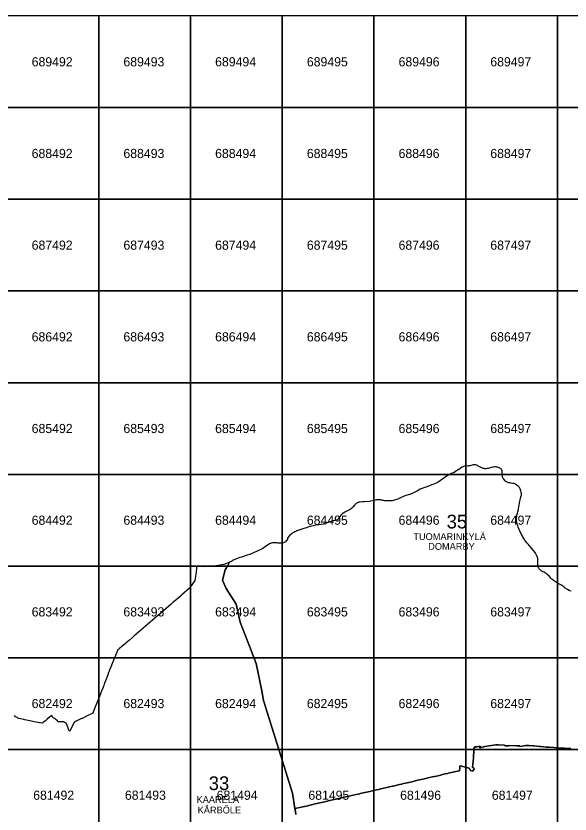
# Model space of a CAD drawing. Extents: x 25485000 to 25520000, y 6656775 to 6690000.
# Drawn here: x 25492097 to 25498138, y 6681295 to 6690000 of the extents above; entities that cross this region are included whole.
import ezdxf

# ---------------------------------------------------------------- set-up
doc = ezdxf.new("R2010")
doc.units = 0
doc.layers.add('Level 63', color=7, linetype='Continuous')

msp = doc.modelspace()

# ---------------------------------------------------------------- linework, layer by layer
at = {"layer": 'Level 63'}
for points in [[(25492000, 6689000), (25493000, 6689000), (25493000, 6690000), (25492000, 6690000)], [(25493000, 6689000), (25494000, 6689000), (25494000, 6690000), (25493000, 6690000)], [(25494000, 6689000), (25495000, 6689000), (25495000, 6690000), (25494000, 6690000)], [(25495000, 6689000), (25496000, 6689000), (25496000, 6690000), (25495000, 6690000)], [(25496000, 6689000), (25497000, 6689000), (25497000, 6690000), (25496000, 6690000)], [(25497000, 6689000), (25498000, 6689000), (25498000, 6690000), (25497000, 6690000)], [(25498000, 6689000), (25499000, 6689000), (25499000, 6690000), (25498000, 6690000)], [(25492000, 6688000), (25493000, 6688000), (25493000, 6689000), (25492000, 6689000)], [(25493000, 6688000), (25494000, 6688000), (25494000, 6689000), (25493000, 6689000)], [(25494000, 6688000), (25495000, 6688000), (25495000, 6689000), (25494000, 6689000)], [(25495000, 6688000), (25496000, 6688000), (25496000, 6689000), (25495000, 6689000)], [(25496000, 6688000), (25497000, 6688000), (25497000, 6689000), (25496000, 6689000)], [(25497000, 6688000), (25498000, 6688000), (25498000, 6689000), (25497000, 6689000)], [(25498000, 6688000), (25499000, 6688000), (25499000, 6689000), (25498000, 6689000)], [(25492000, 6687000), (25493000, 6687000), (25493000, 6688000), (25492000, 6688000)], [(25493000, 6687000), (25494000, 6687000), (25494000, 6688000), (25493000, 6688000)], [(25494000, 6687000), (25495000, 6687000), (25495000, 6688000), (25494000, 6688000)], [(25495000, 6687000), (25496000, 6687000), (25496000, 6688000), (25495000, 6688000)], [(25496000, 6687000), (25497000, 6687000), (25497000, 6688000), (25496000, 6688000)], [(25497000, 6687000), (25498000, 6687000), (25498000, 6688000), (25497000, 6688000)], [(25498000, 6687000), (25499000, 6687000), (25499000, 6688000), (25498000, 6688000)], [(25492000, 6686000), (25493000, 6686000), (25493000, 6687000), (25492000, 6687000)], [(25493000, 6686000), (25494000, 6686000), (25494000, 6687000), (25493000, 6687000)], [(25494000, 6686000), (25495000, 6686000), (25495000, 6687000), (25494000, 6687000)], [(25495000, 6686000), (25496000, 6686000), (25496000, 6687000), (25495000, 6687000)], [(25496000, 6686000), (25497000, 6686000), (25497000, 6687000), (25496000, 6687000)], [(25497000, 6686000), (25498000, 6686000), (25498000, 6687000), (25497000, 6687000)], [(25498000, 6686000), (25499000, 6686000), (25499000, 6687000), (25498000, 6687000)], [(25492000, 6685000), (25493000, 6685000), (25493000, 6686000), (25492000, 6686000)], [(25493000, 6685000), (25494000, 6685000), (25494000, 6686000), (25493000, 6686000)], [(25494000, 6685000), (25495000, 6685000), (25495000, 6686000), (25494000, 6686000)], [(25495000, 6685000), (25496000, 6685000), (25496000, 6686000), (25495000, 6686000)], [(25496000, 6685000), (25497000, 6685000), (25497000, 6686000), (25496000, 6686000)], [(25497000, 6685000), (25498000, 6685000), (25498000, 6686000), (25497000, 6686000)], [(25498000, 6685000), (25499000, 6685000), (25499000, 6686000), (25498000, 6686000)], [(25492000, 6684000), (25493000, 6684000), (25493000, 6685000), (25492000, 6685000)], [(25493000, 6684000), (25494000, 6684000), (25494000, 6685000), (25493000, 6685000)], [(25494000, 6684000), (25495000, 6684000), (25495000, 6685000), (25494000, 6685000)], [(25495000, 6684000), (25496000, 6684000), (25496000, 6685000), (25495000, 6685000)], [(25496000, 6684000), (25497000, 6684000), (25497000, 6685000), (25496000, 6685000)], [(25497000, 6684000), (25498000, 6684000), (25498000, 6685000), (25497000, 6685000)], [(25498000, 6684000), (25499000, 6684000), (25499000, 6685000), (25498000, 6685000)], [(25492000, 6683000), (25493000, 6683000), (25493000, 6684000), (25492000, 6684000)], [(25493000, 6683000), (25494000, 6683000), (25494000, 6684000), (25493000, 6684000)], [(25494000, 6683000), (25495000, 6683000), (25495000, 6684000), (25494000, 6684000)], [(25495000, 6683000), (25496000, 6683000), (25496000, 6684000), (25495000, 6684000)], [(25496000, 6683000), (25497000, 6683000), (25497000, 6684000), (25496000, 6684000)], [(25497000, 6683000), (25498000, 6683000), (25498000, 6684000), (25497000, 6684000)], [(25498000, 6683000), (25499000, 6683000), (25499000, 6684000), (25498000, 6684000)], [(25492000, 6682000), (25493000, 6682000), (25493000, 6683000), (25492000, 6683000)], [(25493000, 6682000), (25494000, 6682000), (25494000, 6683000), (25493000, 6683000)], [(25494000, 6682000), (25495000, 6682000), (25495000, 6683000), (25494000, 6683000)], [(25495000, 6682000), (25496000, 6682000), (25496000, 6683000), (25495000, 6683000)], [(25496000, 6682000), (25497000, 6682000), (25497000, 6683000), (25496000, 6683000)], [(25497000, 6682000), (25498000, 6682000), (25498000, 6683000), (25497000, 6683000)], [(25498000, 6682000), (25499000, 6682000), (25499000, 6683000), (25498000, 6683000)], [(25492000, 6681000), (25493000, 6681000), (25493000, 6682000), (25492000, 6682000)], [(25493000, 6681000), (25494000, 6681000), (25494000, 6682000), (25493000, 6682000)], [(25494000, 6681000), (25495000, 6681000), (25495000, 6682000), (25494000, 6682000)], [(25495000, 6681000), (25496000, 6681000), (25496000, 6682000), (25495000, 6682000)], [(25496000, 6681000), (25497000, 6681000), (25497000, 6682000), (25496000, 6682000)], [(25497000, 6681000), (25498000, 6681000), (25498000, 6682000), (25497000, 6682000)], [(25498000, 6681000), (25499000, 6681000), (25499000, 6682000), (25498000, 6682000)]]:
    msp.add_lwpolyline(points, close=True, dxfattribs=at)
for points in [[(25498148.4, 6683726.5), (25498136.8, 6683730.8), (25498128.7, 6683734.6), (25498111.2, 6683744), (25498086.2, 6683760), (25498071.1, 6683771.5), (25498036.2, 6683793.2), (25497989.5, 6683820.3), (25497978.1, 6683827.7), (25497967.6, 6683835.1), (25497957.9, 6683842.3), (25497948.6, 6683849.8), (25497939.1, 6683857.9), (25497930.1, 6683866.4), (25497912.1, 6683884.4), (25497885, 6683909.9), (25497872.6, 6683920.8), (25497865.7, 6683925.6), (25497854.3, 6683931.3), (25497842.7, 6683936.5), (25497829, 6683943.6), (25497822.6, 6683948), (25497812.1, 6683957.8), (25497802.5, 6683968.9), (25497798.4, 6683975.4), (25497795.4, 6683982), (25497793.2, 6683987.9), (25497789.3, 6684001), (25497786.4, 6684013.5), (25497785.6, 6684020.3), (25497785.7, 6684029.7), (25497787.4, 6684050.4), (25497787.7, 6684064.8), (25497787, 6684076.6), (25497786, 6684082.9), (25497784, 6684092.7), (25497780.8, 6684102.2), (25497776.4, 6684112.2), (25497769.6, 6684124.8), (25497760.8, 6684138.6), (25497752.8, 6684150.4), (25497702.9, 6684214.5), (25497693.5, 6684224.7), (25497683.8, 6684234.5), (25497667.4, 6684252.9), (25497659.7, 6684262.1), (25497652.1, 6684272.1), (25497645.9, 6684280.9), (25497640.1, 6684289.8), (25497634, 6684299.8), (25497609.6, 6684344.3), (25497603.8, 6684355.8), (25497598.2, 6684366.5), (25497573.7, 6684423.7), (25497568.1, 6684438.4), (25497562.6, 6684454.8), (25497559.3, 6684466.4), (25497556.8, 6684477.6), (25497555.3, 6684487.8), (25497554.7, 6684494.6), (25497554.3, 6684505.3), (25497554.2, 6684515.8), (25497555.4, 6684533.4), (25497556.8, 6684543.5), (25497559, 6684553.5), (25497565.7, 6684576.9), (25497569, 6684589.5), (25497575.3, 6684615.2), (25497577.3, 6684627.5), (25497579.2, 6684645.2), (25497582.6, 6684665.6), (25497590.6, 6684708), (25497593.7, 6684722), (25497597.3, 6684736), (25497602.9, 6684753.5), (25497606, 6684765.4), (25497607.4, 6684773.8), (25497607.9, 6684783.6), (25497607.3, 6684795), (25497605.9, 6684805.4), (25497602.9, 6684818.4), (25497599.1, 6684830.1), (25497594.3, 6684841.4), (25497590.2, 6684848.9), (25497585.7, 6684855.5), (25497579.8, 6684862.3), (25497570.9, 6684871.2), (25497560.9, 6684879.7), (25497550.7, 6684887.2), (25497542.5, 6684892.1), (25497534.6, 6684896.1), (25497527.1, 6684899.1), (25497515.4, 6684901.6), (25497495, 6684904.2), (25497483.3, 6684906.2), (25497471.3, 6684908.7), (25497460.8, 6684911.3), (25497454.2, 6684913.7), (25497443.7, 6684918.9), (25497436.7, 6684923.6), (25497434.3, 6684925.8), (25497430, 6684929.7), (25497415.3, 6684946.5), (25497409.4, 6684955.3), (25497406.2, 6684962), (25497402.4, 6684973.1), (25497400.1, 6684984.6), (25497398.9, 6684996.7), (25497398.5, 6685021.1), (25497398, 6685030.3), (25497396.4, 6685039.3), (25497393.3, 6685048.6), (25497389.9, 6685054.6), (25497385.2, 6685060), (25497379.4, 6685064.5), (25497372.6, 6685068.1), (25497359.1, 6685073.5), (25497348.2, 6685077.1), (25497337.4, 6685079.3), (25497325.6, 6685080.2), (25497318.5, 6685080.3), (25497302.2, 6685078.3), (25497293.9, 6685076.8), (25497266.8, 6685070.2), (25497243.5, 6685065.2), (25497231.4, 6685063.3), (25497219, 6685061.7), (25497210, 6685061.4), (25497201.6, 6685062.1), (25497194.7, 6685063.1), (25497184.8, 6685065.7), (25497181.5, 6685066.9), (25497174.8, 6685069.4), (25497159.9, 6685077.1), (25497149.5, 6685083.1), (25497137.8, 6685090.2), (25497128.5, 6685095.8), (25497119.3, 6685100.2), (25497110.8, 6685103), (25497103.7, 6685104.2), (25497093.6, 6685103.9), (25497081.7, 6685102.1), (25497046.8, 6685093.6), (25497034.7, 6685091.4), (25497028.9, 6685090.8), (25497022.4, 6685090.9), (25497010.5, 6685092.5), (25496998.4, 6685092.9), (25496992.9, 6685092.3), (25496987, 6685091), (25496976.5, 6685086.7), (25496962.2, 6685078.4), (25496944.4, 6685067.2), (25496935.4, 6685060.8), (25496918.7, 6685049.1), (25496888.2, 6685029.6), (25496874.6, 6685021.8), (25496861.8, 6685015.7), (25496844.9, 6685008.2), (25496827.6, 6684999.8), (25496808.3, 6684989.4), (25496790.2, 6684979), (25496760.1, 6684957.8), (25496700.7, 6684914.7), (25496693.9, 6684911), (25496686.2, 6684907.2), (25496677.7, 6684903.5), (25496641, 6684889.8), (25496627.8, 6684885.1), (25496618.8, 6684881.8), (25496604.4, 6684875.8), (25496505.2, 6684838.5), (25496484.3, 6684826), (25496473.4, 6684820.1), (25496452.2, 6684808), (25496410.7, 6684786.6), (25496399.1, 6684782.2), (25496361.8, 6684774), (25496348.8, 6684770.6), (25496335.6, 6684766), (25496291.1, 6684745.3), (25496259.4, 6684730.1), (25496247.1, 6684725.1), (25496234.8, 6684720.6), (25496221.7, 6684717.1), (25496209.6, 6684714.6), (25496197, 6684712.5), (25496183.8, 6684711), (25496170.7, 6684710), (25496156.7, 6684709.8), (25496118.5, 6684712.2), (25496106.3, 6684713.6), (25496094.2, 6684716.3), (25496083.3, 6684718.9), (25496075.3, 6684720.3), (25496047.8, 6684722.3), (25496036.1, 6684722.1), (25496023.9, 6684720.4), (25496012.2, 6684718), (25495983, 6684710.9), (25495967.7, 6684707.8), (25495952, 6684705.4), (25495891.5, 6684700.5), (25495874.5, 6684699.1), (25495850.4, 6684698.2), (25495843.3, 6684697.4), (25495833.8, 6684695.7), (25495826.6, 6684693.5), (25495818.1, 6684689.4), (25495809.8, 6684683.5), (25495802, 6684677), (25495789, 6684663.3), (25495773.7, 6684645), (25495766.9, 6684638.4), (25495755.5, 6684628.9), (25495746, 6684621.6), (25495732.2, 6684611.8), (25495726.5, 6684608.5), (25495682.7, 6684586.6), (25495673.1, 6684581.1), (25495663.5, 6684575.3), (25495653.9, 6684568.6), (25495644.7, 6684561), (25495639.6, 6684555.6), (25495627.5, 6684541.8), (25495624, 6684536.6), (25495617.7, 6684526), (25495611.4, 6684513.5), (25495606.9, 6684507.6), (25495602.2, 6684503.8), (25495587.8, 6684501), (25495571.7, 6684497.5), (25495553.3, 6684492.4), (25495543, 6684489), (25495506.3, 6684477.8), (25495498.3, 6684474.8), (25495482.6, 6684468.2), (25495467.5, 6684462.7), (25495460.3, 6684460.5), (25495448.3, 6684457.9), (25495425.6, 6684454.2), (25495401.6, 6684450.5), (25495365.4, 6684444.4), (25495309.1, 6684432.5), (25495297.1, 6684429.3), (25495263.8, 6684418.2), (25495236.3, 6684407.7), (25495213.9, 6684400.3), (25495181.5, 6684390.9), (25495169.4, 6684386.8), (25495158.9, 6684382.8), (25495148, 6684378), (25495136.5, 6684372.5), (25495126.8, 6684366.8), (25495117.1, 6684361), (25495107.3, 6684354.2), (25495098.2, 6684347.4), (25495089, 6684339.7), (25495080.4, 6684331.8), (25495068.6, 6684320.1), (25495064.2, 6684314), (25495059.2, 6684303.4), (25495055.6, 6684292.5), (25495050.8, 6684282.7), (25495043.8, 6684273.2), (25495035.5, 6684264.9), (25495028.7, 6684259.7), (25495020.6, 6684254.9), (25495012.1, 6684251.3), (25495002.1, 6684248.7), (25494990.1, 6684247.6), (25494977.1, 6684247.8), (25494952.9, 6684249.8), (25494940.8, 6684251.4), (25494928.8, 6684252.8), (25494915.8, 6684253.6), (25494903.6, 6684253.4), (25494892.2, 6684252.1), (25494880.3, 6684249.4), (25494872.8, 6684246.7), (25494867, 6684243.9), (25494850.5, 6684233.6), (25494802.5, 6684200.7), (25494787.5, 6684191.5), (25494775.5, 6684184.8), (25494765, 6684179.4), (25494688.4, 6684145.2), (25494652.4, 6684131), (25494607.4, 6684114.3), (25494556.9, 6684096.8), (25494538.4, 6684091.9), (25494481.8, 6684072.7), (25494474.3, 6684069.1), (25494466.1, 6684064.2), (25494454.1, 6684055.8), (25494445.1, 6684050.5), (25494434.8, 6684045), (25494425.3, 6684040.6), (25494401.8, 6684000), (25494379, 6683957.1), (25494349.6, 6683845.6), (25494389.9, 6683753.1), (25494498, 6683585.2), (25494539.7, 6683387.4), (25494642.3, 6683127.1), (25494717.5, 6682937.4), (25494775.8, 6682637.7), (25494796.1, 6682533.7), (25495110.2, 6681520.8), (25495138.2, 6681354.6), (25495172.3, 6681362.1), (25495206.5, 6681370.8), (25495241.2, 6681377.6), (25495259.8, 6681381.5), (25495281.4, 6681385.9), (25495286.7, 6681387), (25495303.3, 6681392), (25495320.2, 6681396.1), (25495357.5, 6681404.4), (25495375.5, 6681408.6), (25495393.5, 6681412.7), (25495429.6, 6681420.9), (25495466.1, 6681429.2), (25495502.4, 6681437.4), (25495534.3, 6681445), (25495566.2, 6681452.6), (25495645.6, 6681471.4), (25495669.4, 6681476.9), (25495693.1, 6681482.3), (25495716.9, 6681487.6), (25495740.8, 6681493), (25495805.9, 6681507.7), (25495830.3, 6681513.1), (25495862.9, 6681520.5), (25495954.5, 6681541.4), (25495979.9, 6681547.2), (25496003.4, 6681552.6), (25496026.1, 6681557.9), (25496051.9, 6681564), (25496071.5, 6681568.4), (25496075.9, 6681569.4), (25496106.2, 6681576.2), (25496140.1, 6681583.9), (25496170.6, 6681590.9), (25496202.3, 6681598.2), (25496209.6, 6681600), (25496276.9, 6681616), (25496299.5, 6681621.2), (25496322, 6681626.5), (25496344.6, 6681631.7), (25496379.4, 6681639.8), (25496413.5, 6681647.7), (25496478.8, 6681662.5), (25496513.1, 6681670.4), (25496546.7, 6681678.3), (25496605.4, 6681692.1), (25496639.4, 6681699.9), (25496680.9, 6681708.7), (25496713.3, 6681716.4), (25496746.2, 6681724.3), (25496777, 6681731.4), (25496802, 6681737.2), (25496810.3, 6681739.1), (25496826.3, 6681742.8), (25496874.9, 6681754.2), (25496931.7, 6681767.2), (25496932.1, 6681767), (25496935.5, 6681801.9), (25496936.8, 6681815.1), (25496943.2, 6681819.7), (25497036.7, 6681796.3), (25497052.7, 6681769.7), (25497075.9, 6681763.9), (25497091.8, 6681784.7), (25497090.1, 6681799.6), (25497074.9, 6681803.4), (25497077.8, 6681838.8), (25497079.9, 6681863.7), (25497084, 6681913.5), (25497086.8, 6681946.9), (25497087.2, 6681952.6), (25497089.6, 6681982.6), (25497091.6, 6682007.3), (25497093, 6682024.3), (25497102.7, 6682025.9), (25497122.9, 6682029.3), (25497156.9, 6682034.9), (25497155.3, 6682015.5), (25497195.2, 6682027.4), (25497207.1, 6682030.9), (25497210.1, 6682031.4), (25497255.4, 6682038.3), (25497280.5, 6682042.3), (25497302.8, 6682045.6), (25497330, 6682049.6), (25497343.3, 6682049.2), (25497358.8, 6682048.4), (25497423.7, 6682046.1), (25497426.4, 6682042), (25497426.3, 6682040), (25497469.8, 6682037.9), (25497470.2, 6682043.8), (25497554.8, 6682039.5), (25497586, 6682038), (25497590.4, 6682030.7), (25497637.5, 6682040), (25497655.8, 6682043.5), (25497678.4, 6682041.5), (25497689.3, 6682040.8), (25497730.6, 6682038.1), (25497736.6, 6682037.5), (25497742.3, 6682037), (25497772.2, 6682034.4), (25497807.1, 6682031.1), (25497819.1, 6682030.4), (25497878.8, 6682025.3), (25497881.4, 6682025.1), (25497909.6, 6682023.1), (25498009.3, 6682017.8), (25498145.5, 6682010.5)], [(25495149.3, 6681289.5), (25495143.9, 6681321.9), (25495138.2, 6681354.6), (25495110.2, 6681520.8), (25494796.1, 6682533.7), (25494775.8, 6682637.7), (25494717.5, 6682937.4), (25494642.3, 6683127.1), (25494539.7, 6683387.4), (25494498, 6683585.2), (25494389.9, 6683753.1), (25494349.6, 6683845.6), (25494379, 6683957.1), (25494401.8, 6684000), (25494425.3, 6684040.6), (25494385, 6684025), (25494362.8, 6684017.7), (25494342.8, 6684011.8), (25494328.3, 6684008.9), (25494299.8, 6684004.6), (25494250.4, 6683998.2), (25494207.7, 6683993.8), (25494186.7, 6683993), (25494150.9, 6683992.4), (25494089.7, 6683995.1), (25494068.1, 6683996), (25494066.7, 6683984.5), (25494066.4, 6683981.9), (25494065.2, 6683972.7), (25494060.6, 6683935.5), (25494051.4, 6683865.5), (25494048.7, 6683842.4), (25493989.3, 6683757.9), (25493906.2, 6683685.6), (25493903.1, 6683682.9), (25493892.7, 6683673.9), (25493864.6, 6683649.3), (25493839.7, 6683628.9), (25493811.9, 6683604.6), (25493788.9, 6683584.5), (25493680.7, 6683489.9), (25493677.5, 6683487.1), (25493671.4, 6683481.9), (25493641.1, 6683457), (25493635, 6683451.7), (25493632.5, 6683449.6), (25493614.3, 6683433.9), (25493610.5, 6683430.7), (25493383.6, 6683234.9), (25493366.9, 6683220.6), (25493333.1, 6683191.5), (25493298.3, 6683161.8), (25493295.9, 6683159.6), (25493292, 6683156.4), (25493250.8, 6683121.2), (25493226, 6683099.8), (25493225.5, 6683099.6), (25493219.5, 6683094.4), (25493213.5, 6683088.7), (25493211.9, 6683087.7), (25493204.6, 6683081.4), (25493203, 6683077.4), (25493191.9, 6683049.6), (25493185.8, 6683034.4), (25493181.4, 6683023.3), (25493175, 6683007.3), (25493139.5, 6682918.8), (25493137.8, 6682914.3), (25493125.6, 6682883.5), (25493114.4, 6682855.1), (25493112.3, 6682849.7), (25493109.6, 6682842.9), (25493107.7, 6682838.1), (25493099.1, 6682814.8), (25493083.1, 6682773.8), (25493072.5, 6682746), (25493063.3, 6682722.3), (25493058.2, 6682709.3), (25493046.2, 6682678.3), (25493032, 6682641.6), (25493031.3, 6682639.7), (25493026.9, 6682628.2), (25493003.1, 6682567.1), (25492999.3, 6682557.5), (25492982.4, 6682514.3), (25492961.9, 6682462.3), (25492935.5, 6682394.9), (25492872.1, 6682364.4), (25492840.4, 6682349.2), (25492818, 6682338.3), (25492805.3, 6682332.1), (25492753.4, 6682307.3), (25492750.5, 6682305.9), (25492741, 6682301.4), (25492733.1, 6682297.6), (25492683.7, 6682198.9), (25492673.9, 6682207.4), (25492670.1, 6682212.9), (25492668.9, 6682216.9), (25492669, 6682225.3), (25492668.2, 6682230), (25492667.9, 6682231.3), (25492661.6, 6682248.2), (25492660.3, 6682250.8), (25492651.1, 6682269.7), (25492643, 6682284.4), (25492638.8, 6682288.4), (25492625.9, 6682294.5), (25492614.6, 6682299.5), (25492607, 6682300.1), (25492584.9, 6682299.9), (25492575.7, 6682299.1), (25492566.4, 6682300.3), (25492559, 6682302.1), (25492554.1, 6682304.4), (25492548.3, 6682309.6), (25492536.1, 6682323.6), (25492529.1, 6682329.1), (25492517.4, 6682335.9), (25492504.3, 6682345.8), (25492497.9, 6682352.1), (25492493.5, 6682360.3), (25492486.6, 6682370.5), (25492463.5, 6682350.7), (25492432.9, 6682324.7), (25492414.9, 6682309.4), (25492412.9, 6682307.7), (25492394.2, 6682291.8), (25492385.8, 6682284.6), (25492361.5, 6682289.5), (25492355, 6682290.9), (25492195.2, 6682323.1), (25492183, 6682325.6), (25492126.9, 6682336.9), (25492117.7, 6682342.2), (25492108.5, 6682347.6), (25492100.5, 6682352.2), (25492077.7, 6682365.4)], [(25498145.5, 6682010.5), (25498009.3, 6682017.8), (25497909.6, 6682023.1), (25497881.4, 6682025.1), (25497878.8, 6682025.3), (25497819.1, 6682030.4), (25497807.1, 6682031.1), (25497772.2, 6682034.4), (25497742.3, 6682037), (25497736.6, 6682037.5), (25497730.6, 6682038.1), (25497689.3, 6682040.8), (25497678.4, 6682041.5), (25497655.8, 6682043.5), (25497637.5, 6682040), (25497590.4, 6682030.7), (25497586, 6682038), (25497554.8, 6682039.5), (25497470.2, 6682043.8), (25497469.8, 6682037.9), (25497426.3, 6682040), (25497426.4, 6682042), (25497423.7, 6682046.1), (25497358.8, 6682048.4), (25497343.3, 6682049.2), (25497330, 6682049.6), (25497302.8, 6682045.6), (25497280.5, 6682042.3), (25497255.4, 6682038.3), (25497210.1, 6682031.4), (25497207.1, 6682030.9), (25497195.2, 6682027.4), (25497155.3, 6682015.5), (25497156.9, 6682034.9), (25497122.9, 6682029.3), (25497102.7, 6682025.9), (25497093, 6682024.3), (25497091.6, 6682007.3), (25497089.6, 6681982.6), (25497087.2, 6681952.6), (25497086.8, 6681946.9), (25497084, 6681913.5), (25497079.9, 6681863.7), (25497077.8, 6681838.8), (25497074.9, 6681803.4), (25497090.1, 6681799.6), (25497091.8, 6681784.7), (25497075.9, 6681763.9), (25497052.7, 6681769.7), (25497036.7, 6681796.3), (25496943.2, 6681819.7), (25496936.8, 6681815.1), (25496935.5, 6681801.9), (25496932.1, 6681767), (25496931.7, 6681767.2), (25496874.9, 6681754.2), (25496826.3, 6681742.8), (25496810.3, 6681739.1), (25496802, 6681737.2), (25496777, 6681731.4), (25496746.2, 6681724.3), (25496713.3, 6681716.4), (25496680.9, 6681708.7), (25496639.4, 6681699.9), (25496605.4, 6681692.1), (25496546.7, 6681678.3), (25496513.1, 6681670.4), (25496478.8, 6681662.5), (25496413.5, 6681647.7), (25496379.4, 6681639.8), (25496344.6, 6681631.7), (25496322, 6681626.5), (25496299.5, 6681621.2), (25496276.9, 6681616), (25496209.6, 6681600), (25496202.3, 6681598.2), (25496170.6, 6681590.9), (25496140.1, 6681583.9), (25496106.2, 6681576.2), (25496075.9, 6681569.4), (25496071.5, 6681568.4), (25496051.9, 6681564), (25496026.1, 6681557.9), (25496003.4, 6681552.6), (25495979.9, 6681547.2), (25495954.5, 6681541.4), (25495862.9, 6681520.5), (25495830.3, 6681513.1), (25495805.9, 6681507.7), (25495740.8, 6681493), (25495716.9, 6681487.6), (25495693.1, 6681482.3), (25495669.4, 6681476.9), (25495645.6, 6681471.4), (25495566.2, 6681452.6), (25495534.3, 6681445), (25495502.4, 6681437.4), (25495466.1, 6681429.2), (25495429.6, 6681420.9), (25495393.5, 6681412.7), (25495375.5, 6681408.6), (25495357.5, 6681404.4), (25495320.2, 6681396.1), (25495303.3, 6681392), (25495286.7, 6681387), (25495281.4, 6681385.9), (25495259.8, 6681381.5), (25495241.2, 6681377.6), (25495206.5, 6681370.8), (25495172.3, 6681362.1), (25495138.2, 6681354.6), (25495143.9, 6681321.9), (25495149.3, 6681289.5)]]:
    msp.add_lwpolyline(points, dxfattribs=at)

# ---------------------------------------------------------------- texts
for s, height, p in [('689492', 100, (25492268.5, 6689450)), ('689493', 100, (25493268.5, 6689450)), ('689494', 100, (25494268.5, 6689450)), ('689495', 100, (25495268.5, 6689450)), ('689496', 100, (25496268.5, 6689450)), ('689497', 100, (25497268.5, 6689450)), ('688492', 100, (25492268.5, 6688450)), ('688493', 100, (25493268.5, 6688450)), ('688494', 100, (25494268.5, 6688450)), ('688495', 100, (25495268.5, 6688450)), ('688496', 100, (25496268.5, 6688450)), ('688497', 100, (25497268.5, 6688450)), ('687492', 100, (25492268.5, 6687450)), ('687493', 100, (25493268.5, 6687450)), ('687494', 100, (25494268.5, 6687450)), ('687495', 100, (25495268.5, 6687450)), ('687496', 100, (25496268.5, 6687450)), ('687497', 100, (25497268.5, 6687450)), ('686492', 100, (25492268.5, 6686450)), ('686493', 100, (25493268.5, 6686450)), ('686494', 100, (25494268.5, 6686450)), ('686495', 100, (25495268.5, 6686450)), ('686496', 100, (25496268.5, 6686450)), ('686497', 100, (25497268.5, 6686450)), ('685492', 100, (25492268.5, 6685450)), ('685493', 100, (25493268.5, 6685450)), ('685494', 100, (25494268.5, 6685450)), ('685495', 100, (25495268.5, 6685450)), ('685496', 100, (25496268.5, 6685450)), ('685497', 100, (25497268.5, 6685450)), ('684492', 100, (25492268.5, 6684450)), ('684493', 100, (25493268.5, 6684450)), ('684494', 100, (25494268.5, 6684450)), ('684495', 100, (25495268.5, 6684450)), ('684496', 100, (25496268.5, 6684450)), ('35', 150, (25496792.5, 6684409.7)), ('684497', 100, (25497268.5, 6684450)), ('TUOMARINKYLÄ', 75, (25496429.4, 6684283)), ('DOMARBY', 75, (25496591.4, 6684176.8)), ('683492', 100, (25492268.5, 6683450)), ('683493', 100, (25493268.5, 6683450)), ('683494', 100, (25494268.5, 6683450)), ('683495', 100, (25495268.5, 6683450)), ('683496', 100, (25496268.5, 6683450)), ('683497', 100, (25497268.5, 6683450)), ('682492', 100, (25492268.5, 6682450)), ('682493', 100, (25493268.5, 6682450)), ('682494', 100, (25494268.5, 6682450)), ('682495', 100, (25495268.5, 6682450)), ('682496', 100, (25496268.5, 6682450)), ('682497', 100, (25497268.5, 6682450)), ('33', 150, (25494199, 6681555.7)), ('681492', 100, (25492285.1, 6681450)), ('681493', 100, (25493285.1, 6681450)), ('681494', 100, (25494285.1, 6681450)), ('681495', 100, (25495285.1, 6681450)), ('681496', 100, (25496285.1, 6681450)), ('681497', 100, (25497285.1, 6681450)), ('KAARELA', 75, (25494066.3, 6681415.3)), ('KÅRBÖLE', 75, (25494077.9, 6681300.7))]:
    msp.add_text(s, height=height, dxfattribs=at).set_placement(p)

doc.saveas('drawing.dxf')
